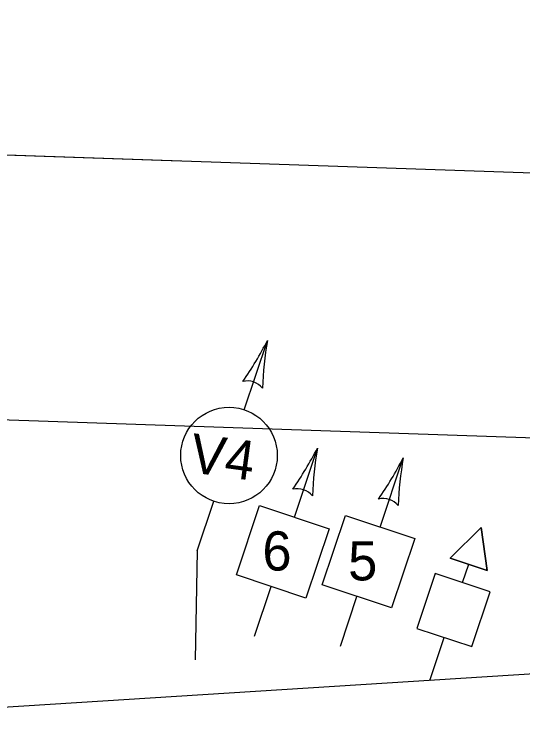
# Model space of a CAD drawing. Extents: x 647787 to 668496, y 640478 to 654412.
# Drawn here: x 661747.7 to 661789.9, y 647252.4 to 647310.9 of the extents above; entities that cross this region are included whole.
import ezdxf

# ---------------------------------------------------------------- set-up
doc = ezdxf.new("R2010")
doc.units = 0
for name, color, linetype in [('Default', 7, 'Continuous'), ('TEMP_SIGNAL_HEAD_STAGE 2', 7, 'Continuous'), ('TEMP_SIGNAL_HEAD_Stage 3', 7, 'Continuous'), ('TEMP_SIGNAL_HEAD_STAGE 3 SHILO', 7, 'Continuous'), ('TEMP_SIGNAL_HEAD_STAGE 4 SHILO', 7, 'Continuous'), ('TEMP_SIGNAL_HEAD_STAGE4', 7, 'Continuous'), ('TEMP_SIGNAL_POLES_STAGES 3-4', 7, 'Continuous'), ('TEXT_TEMP_SIGNAL_POLES_STAGE 2', 7, 'Continuous'), ('TEXT_TEMP_SIGNAL_POLES_STAGE 3', 7, 'Continuous'), ('TEXT_TEMP_SIGNAL_POLES_STAGE 4', 7, 'Continuous')]:
    doc.layers.add(name, color=color, linetype=linetype)

msp = doc.modelspace()

# ---------------------------------------------------------------- linework, layer by layer
at = {"layer": 'Default'}
for points in [[(662136.439, 647331.769), (661882.019, 647294.613), (661114.402, 647320.889)], [(662108.288, 647310.771), (661853.868, 647273.614), (661086.251, 647299.89)], [(661761.55, 647298.737), (661606.212, 647304.054)], [(661761.55, 647298.737), (661606.212, 647304.054)]]:
    msp.add_lwpolyline(points, dxfattribs=at)
at = {"layer": 'TEMP_SIGNAL_HEAD_STAGE 2'}
for p, q in [((661766.802, 647278.124), (661768.721, 647283.876)), ((661770.95, 647269.215), (661772.862, 647274.945)), ((661778.057, 647268.399), (661779.969, 647274.129)), ((661762.898, 647266.427), (661764.269, 647270.535)), ((661762.898, 647266.427), (661762.737, 647257.378)), ((661767.655, 647259.34), (661769.031, 647263.464)), ((661774.762, 647258.524), (661776.138, 647262.648))]:
    msp.add_line(p, q, dxfattribs=at)
for points in [[(661771.907, 647262.504), (661766.154, 647264.423), (661768.073, 647270.175), (661773.826, 647268.255)], [(661779.014, 647261.688), (661773.261, 647263.607), (661775.18, 647269.359), (661780.933, 647267.439)]]:
    msp.add_lwpolyline(points, close=True, dxfattribs=at)
msp.add_circle((661765.535, 647274.33), 4, dxfattribs=at)
for centre, radius, start, end in [((661742.476, 647297.28), 29.47, 325.20888, 332.94699), ((661797.76, 647278.842), 29.472, 170.16456, 177.90267), ((661767.055, 647278.88), 1.629, 39.69791, 103.39255), ((661746.617, 647288.353), 29.472, 325.20141, 332.93952), ((661801.901, 647269.906), 29.472, 170.15616, 177.89427), ((661753.724, 647287.536), 29.472, 325.20141, 332.93952), ((661809.008, 647269.09), 29.472, 170.15616, 177.89427), ((661771.195, 647269.949), 1.629, 39.70052, 103.39516), ((661778.302, 647269.133), 1.629, 39.70052, 103.39516)]:
    msp.add_arc(centre, radius, start, end, dxfattribs=at)
at = {"layer": 'TEMP_SIGNAL_HEAD_Stage 3'}
for p, q in [((661766.802, 647278.124), (661768.721, 647283.876)), ((661770.95, 647269.215), (661772.862, 647274.945)), ((661778.057, 647268.399), (661779.969, 647274.129)), ((661762.898, 647266.427), (661764.269, 647270.535)), ((661762.898, 647266.427), (661762.737, 647257.378)), ((661767.655, 647259.34), (661769.031, 647263.464)), ((661774.762, 647258.524), (661776.138, 647262.648))]:
    msp.add_line(p, q, dxfattribs=at)
for points in [[(661771.907, 647262.504), (661766.154, 647264.423), (661768.073, 647270.175), (661773.826, 647268.255)], [(661779.014, 647261.688), (661773.261, 647263.607), (661775.18, 647269.359), (661780.933, 647267.439)]]:
    msp.add_lwpolyline(points, close=True, dxfattribs=at)
msp.add_circle((661765.535, 647274.33), 4, dxfattribs=at)
for centre, radius, start, end in [((661742.476, 647297.28), 29.47, 325.20888, 332.94699), ((661797.76, 647278.842), 29.472, 170.16456, 177.90267), ((661767.055, 647278.88), 1.629, 39.69791, 103.39255), ((661746.617, 647288.353), 29.472, 325.20141, 332.93952), ((661801.901, 647269.906), 29.472, 170.15616, 177.89427), ((661753.724, 647287.536), 29.472, 325.20141, 332.93952), ((661809.008, 647269.09), 29.472, 170.15616, 177.89427), ((661771.195, 647269.949), 1.629, 39.70052, 103.39516), ((661778.302, 647269.133), 1.629, 39.70052, 103.39516)]:
    msp.add_arc(centre, radius, start, end, dxfattribs=at)
at = {"layer": 'TEMP_SIGNAL_HEAD_STAGE 3 SHILO'}
for points in [[(661786.938, 647264.798), (661783.867, 647265.822), (661786.423, 647268.37), (661786.938, 647264.798)], [(661786.938, 647264.798), (661783.867, 647265.822), (661786.423, 647268.37), (661786.938, 647264.798)], [(661784.896, 647263.792), (661785.402, 647265.31)], [(661784.896, 647263.792), (661785.402, 647265.31)], [(661782.189, 647255.681), (661783.376, 647259.239)], [(661782.189, 647255.681), (661783.376, 647259.239)]]:
    msp.add_lwpolyline(points, dxfattribs=at)
for points in [[(661786.423, 647268.37), (661783.867, 647265.822), (661786.938, 647264.798)], [(661786.423, 647268.37), (661783.867, 647265.822), (661786.938, 647264.798)], [(661781.1, 647259.999), (661785.653, 647258.479), (661787.172, 647263.033), (661782.619, 647264.552)], [(661781.1, 647259.999), (661785.653, 647258.479), (661787.172, 647263.033), (661782.619, 647264.552)]]:
    msp.add_lwpolyline(points, close=True, dxfattribs=at)
at = {"layer": 'TEMP_SIGNAL_HEAD_STAGE 4 SHILO'}
for points in [[(661786.938, 647264.798), (661783.867, 647265.822), (661786.423, 647268.37), (661786.938, 647264.798)], [(661786.938, 647264.798), (661783.867, 647265.822), (661786.423, 647268.37), (661786.938, 647264.798)], [(661784.896, 647263.792), (661785.402, 647265.31)], [(661784.896, 647263.792), (661785.402, 647265.31)], [(661782.189, 647255.681), (661783.376, 647259.239)], [(661782.189, 647255.681), (661783.376, 647259.239)]]:
    msp.add_lwpolyline(points, dxfattribs=at)
for points in [[(661786.423, 647268.37), (661783.867, 647265.822), (661786.938, 647264.798)], [(661786.423, 647268.37), (661783.867, 647265.822), (661786.938, 647264.798)], [(661781.1, 647259.999), (661785.653, 647258.479), (661787.172, 647263.033), (661782.619, 647264.552)], [(661781.1, 647259.999), (661785.653, 647258.479), (661787.172, 647263.033), (661782.619, 647264.552)]]:
    msp.add_lwpolyline(points, close=True, dxfattribs=at)
at = {"layer": 'TEMP_SIGNAL_HEAD_STAGE4'}
for p, q in [((661766.802, 647278.124), (661768.721, 647283.876)), ((661770.95, 647269.215), (661772.862, 647274.945)), ((661778.057, 647268.399), (661779.969, 647274.129)), ((661762.898, 647266.427), (661764.269, 647270.535)), ((661762.898, 647266.427), (661762.737, 647257.378)), ((661767.655, 647259.34), (661769.031, 647263.464)), ((661774.762, 647258.524), (661776.138, 647262.648))]:
    msp.add_line(p, q, dxfattribs=at)
for points in [[(661771.907, 647262.504), (661766.154, 647264.423), (661768.073, 647270.175), (661773.826, 647268.255)], [(661779.014, 647261.688), (661773.261, 647263.607), (661775.18, 647269.359), (661780.933, 647267.439)]]:
    msp.add_lwpolyline(points, close=True, dxfattribs=at)
msp.add_circle((661765.535, 647274.33), 4, dxfattribs=at)
for centre, radius, start, end in [((661742.476, 647297.28), 29.47, 325.20888, 332.94699), ((661797.76, 647278.842), 29.472, 170.16456, 177.90267), ((661767.055, 647278.88), 1.629, 39.69791, 103.39255), ((661746.617, 647288.353), 29.472, 325.20141, 332.93952), ((661801.901, 647269.906), 29.472, 170.15616, 177.89427), ((661753.724, 647287.536), 29.472, 325.20141, 332.93952), ((661809.008, 647269.09), 29.472, 170.15616, 177.89427), ((661771.195, 647269.949), 1.629, 39.70052, 103.39516), ((661778.302, 647269.133), 1.629, 39.70052, 103.39516)]:
    msp.add_arc(centre, radius, start, end, dxfattribs=at)
at = {"layer": 'TEMP_SIGNAL_POLES_STAGES 3-4'}
msp.add_line((661857.996, 647260.481), (661730.488, 647252.408), dxfattribs=at)
msp.add_line((661857.996, 647260.481), (661730.488, 647252.408), dxfattribs=at)

# ---------------------------------------------------------------- texts
at = {"layer": 'TEXT_TEMP_SIGNAL_POLES_STAGE 2'}
msp.add_text('V4', height=3.25, rotation=352.315, dxfattribs=at).set_placement((661762.169, 647272.957))
for s, p in [('6', (661768.303, 647264.789)), ('5', (661775.41, 647263.973))]:
    msp.add_text(s, height=3.25, dxfattribs=at).set_placement(p)
at = {"layer": 'TEXT_TEMP_SIGNAL_POLES_STAGE 3'}
msp.add_text('V4', height=3.25, rotation=352.315, dxfattribs=at).set_placement((661762.169, 647272.957))
for s, p in [('6', (661768.303, 647264.789)), ('5', (661775.41, 647263.973))]:
    msp.add_text(s, height=3.25, dxfattribs=at).set_placement(p)
at = {"layer": 'TEXT_TEMP_SIGNAL_POLES_STAGE 4'}
msp.add_text('V4', height=3.25, rotation=352.315, dxfattribs=at).set_placement((661762.169, 647272.957))
for s, p in [('6', (661768.303, 647264.789)), ('5', (661775.41, 647263.973))]:
    msp.add_text(s, height=3.25, dxfattribs=at).set_placement(p)

doc.saveas('drawing.dxf')
